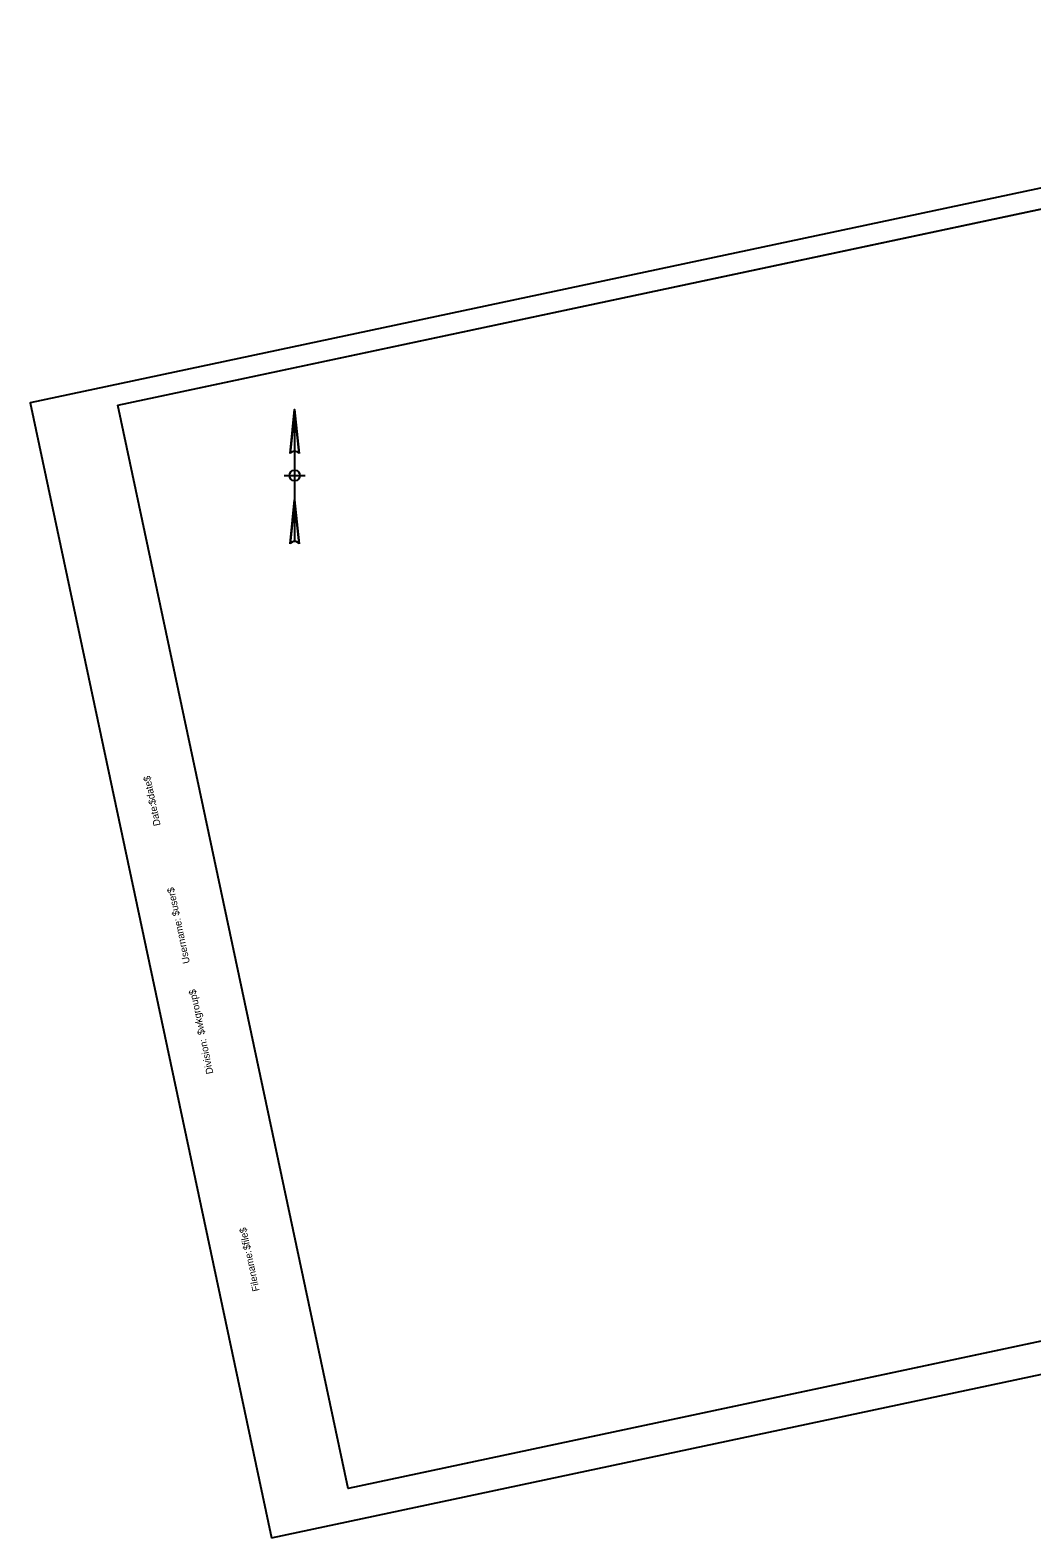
# Model space of a CAD drawing. Extents: x 1742668 to 1743618, y 462122 to 462837.
# Drawn here: x 1742668 to 1743143, y 462122 to 462837 of the extents above; entities that cross this region are included whole.
import ezdxf

# ---------------------------------------------------------------- set-up
doc = ezdxf.new("R2010")
doc.units = 0
for name, color, linetype in [('D_Text_Standard', 7, 'Continuous'), ('DIMENSIONS', 7, 'Continuous'), ('M_Fencing', 7, 'Continuous'), ('M_Misc_MiscItems', 7, 'Continuous')]:
    doc.layers.add(name, color=color, linetype=linetype)

msp = doc.modelspace()

# ---------------------------------------------------------------- linework, layer by layer
at = {"layer": 'D_Text_Standard'}
for p, q in [((1742791.32, 462636.04), (1742793.41, 462656.87)), ((1742793.41, 462656.87), (1742793.41, 462594.37)), ((1742793.41, 462656.87), (1742795.49, 462636.04)), ((1742788.41, 462625.62), (1742798.41, 462625.62)), ((1742791.32, 462593.26), (1742793.41, 462614.09)), ((1742793.41, 462614.09), (1742795.49, 462593.26))]:
    msp.add_line(p, q, dxfattribs=at)
for points in [[(1742795.49, 462636.04), (1742793.41, 462656.87), (1742792.36, 462646.46), (1742791.32, 462636.04)], [(1742795.49, 462593.26), (1742793.41, 462614.09), (1742792.36, 462603.67), (1742791.32, 462593.26)]]:
    msp.add_lwpolyline(points, dxfattribs=at)
msp.add_circle((1742793.41, 462625.62), 2.5, dxfattribs=at)
for centre in [(1742793.41, 462634.66), (1742793.41, 462634.66), (1742793.41, 462591.87), (1742793.41, 462591.87)]:
    msp.add_arc(centre, 2.5, 33.55731, 146.44269, dxfattribs=at)
at = {"layer": 'DIMENSIONS'}
msp.add_lwpolyline([(1742709.65, 462658.94), (1743492.17, 462825.27), (1743601.32, 462311.74), (1742818.8, 462145.41)], close=True, dxfattribs=at)
at = {"layer": 'M_Fencing'}
msp.add_lwpolyline([(1742782.4, 462122.04), (1743613.83, 462298.76), (1743499.47, 462836.74), (1742668.05, 462660.02)], close=True, dxfattribs=at)
at = {"layer": 'M_Misc_MiscItems'}
msp.add_lwpolyline([(1742709.65, 462658.94), (1743443.26, 462814.87), (1743552.41, 462301.34), (1742818.8, 462145.41)], close=True, dxfattribs=at)

# ---------------------------------------------------------------- texts
at = {"layer": 'DIMENSIONS'}
for s, p in [('$date$', (1742727.73, 462470.1)), ('Date:', (1742729.9, 462459.88)), ('$user$', (1742738.97, 462417.21)), ('Username:', (1742743.78, 462394.6)), ('$wkgroup$', (1742750.95, 462360.86)), ('Division:', (1742754.9, 462342.26)), ('$file$', (1742772.62, 462258.92)), ('Filename:', (1742776.81, 462239.22))]:
    msp.add_text(s, height=3.348, rotation=102, dxfattribs=at).set_placement(p)

doc.saveas('drawing.dxf')
